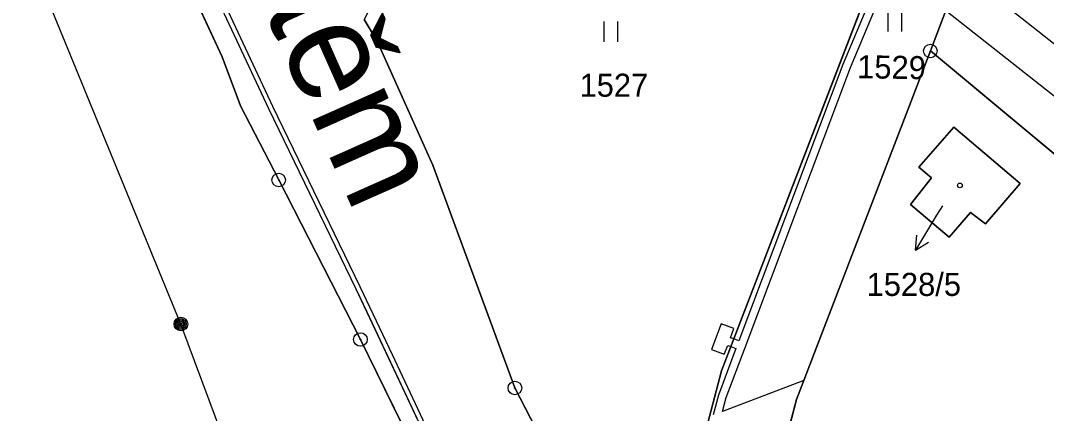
# Model space of a CAD drawing. Extents: x -689422 to -685210, y -987725 to -982160.
# Drawn here: x -687751.8 to -687676.3, y -985280.3 to -985251.4 of the extents above; entities that cross this region are included whole.
import ezdxf

# ---------------------------------------------------------------- set-up
doc = ezdxf.new("R2010")
doc.units = 0
for name, color, linetype in [('KN_Budovy', 7, 'Continuous'), ('KN_Hranice_parcel', 7, 'Continuous'), ('KN_Parcelni cisla', 7, 'Continuous'), ('KN_Parcelni cisla_sipky', 7, 'Continuous'), ('KN_Polygon parcely', 7, 'Continuous'), ('KN_Popisy_pomistni nazvy nazvy ulic', 7, 'Continuous'), ('KN_Pozemkove predmety', 7, 'Continuous'), ('KN_POZEMKY_ORNA PUDA', 7, 'Continuous'), ('KN_POZEMKY_OSTATNI PLOCHA', 7, 'Continuous'), ('KN_POZEMKY_TTP', 7, 'Continuous'), ('KN_POZEMKY_ZASTAVENA PLOCHA', 7, 'Continuous'), ('KN_VYUZITI_17_ostatni plocha_ostatni komunikace', 7, 'Continuous'), ('KN_Věcná břemena k části', 7, 'Continuous'), ('KN_Značky bodu BP', 7, 'Continuous'), ('KN_Značky budov', 7, 'Continuous'), ('KN_Značky kultur', 7, 'Continuous')]:
    doc.layers.add(name, color=color, linetype=linetype)

msp = doc.modelspace()

# ---------------------------------------------------------------- linework, layer by layer
at = {"layer": 'KN_Budovy'}
msp.add_lwpolyline([(-687685.66, -985262.2), (-687684.72, -985263), (-687686.28, -985264.95), (-687683.43, -985267.36), (-687681.85, -985265.54), (-687680.76, -985266.39), (-687678.19, -985263.41), (-687683.07, -985259.26)], close=True, dxfattribs=at)
at = {"layer": 'KN_Hranice_parcel'}
msp.add_line((-687684.81, -985253.65), (-687660.69, -985273.71), dxfattribs=at)
for points in [[(-687678.29, -985374.8), (-687680.11, -985371.33), (-687690.18, -985350.53), (-687698.39, -985334.89), (-687706.44, -985319.16), (-687712.04, -985306.92), (-687713.81, -985302.68), (-687714.34, -985301.44), (-687721.19, -985286.31), (-687726.79, -985274.9), (-687732.81, -985263.15), (-687735.61, -985257.68), (-687736.98, -985254.09), (-687739.8, -985247.97), (-687746.27, -985237.32), (-687750.23, -985231.18), (-687753.34, -985220.89), (-687754.9, -985213.17), (-687756.81, -985206.35), (-687758.16, -985197.59), (-687758.19, -985196.42)], [(-687684.81, -985253.65), (-687683.66, -985250.66), (-687677.81, -985238.56)], [(-687705.55, -985297.58), (-687700.19, -985277.21), (-687689.27, -985248.82)], [(-687726.51, -985251.33), (-687725.56, -985252.93), (-687721.45, -985262.05), (-687715.41, -985278.47), (-687705.55, -985297.58)], [(-687701.56, -985305.65), (-687698.06, -985292.26), (-687694.68, -985279.32), (-687684.81, -985253.65)], [(-687683.43, -985267.36), (-687686.28, -985264.95), (-687684.72, -985263), (-687685.66, -985262.2), (-687683.07, -985259.26), (-687678.19, -985263.41), (-687680.76, -985266.39), (-687681.85, -985265.54), (-687683.43, -985267.36)]]:
    msp.add_lwpolyline(points, dxfattribs=at)
at = {"layer": 'KN_Parcelni cisla_sipky'}
for p, q in [((-687683.92, -985265.05), (-687684.35, -985265.75)), ((-687684.35, -985265.75), (-687685.896, -985268.322)), ((-687685.896, -985268.322), (-687685.809, -985267.206)), ((-687685.896, -985268.322), (-687684.951, -985267.722))]:
    msp.add_line(p, q, dxfattribs=at)
at = {"layer": 'KN_Polygon parcely'}
for points in [[(-687703.73, -985301.1), (-687701.56, -985305.65), (-687698.06, -985292.26), (-687694.68, -985279.32), (-687684.81, -985253.65), (-687683.66, -985250.66), (-687677.81, -985238.56), (-687665.95, -985214.02), (-687671.26, -985211.45), (-687689.27, -985248.82), (-687700.19, -985277.21), (-687705.55, -985297.58)], [(-687700.19, -985277.21), (-687689.27, -985248.82), (-687710.55, -985219.47), (-687726.51, -985251.33), (-687725.56, -985252.93), (-687721.45, -985262.05), (-687715.41, -985278.47), (-687705.55, -985297.58)], [(-687660.69, -985273.71), (-687649.8, -985254.23), (-687655.11, -985251.26), (-687677.81, -985238.56), (-687683.66, -985250.66), (-687684.81, -985253.65)], [(-687660.69, -985273.71), (-687684.81, -985253.65), (-687694.68, -985279.32), (-687698.06, -985292.26), (-687701.56, -985305.65), (-687697.77, -985313.58), (-687696.15, -985316.45), (-687692.92, -985322.65), (-687657.88, -985303.61), (-687653.06, -985312.83), (-687645.42, -985295.51), (-687642.23, -985289.06)], [(-687683.43, -985267.36), (-687681.85, -985265.54), (-687680.76, -985266.39), (-687678.19, -985263.41), (-687683.07, -985259.26), (-687685.66, -985262.2), (-687684.72, -985263), (-687686.28, -985264.95)], [(-687683.43, -985267.36), (-687686.28, -985264.95), (-687684.72, -985263), (-687685.66, -985262.2), (-687683.07, -985259.26), (-687678.19, -985263.41), (-687680.76, -985266.39), (-687681.85, -985265.54)]]:
    msp.add_lwpolyline(points, close=True, dxfattribs=at)
for points in [[(-687690.18, -985350.53), (-687698.39, -985334.89), (-687706.44, -985319.16), (-687712.04, -985306.92), (-687713.81, -985302.68), (-687714.34, -985301.44), (-687721.19, -985286.31), (-687726.79, -985274.9), (-687732.81, -985263.15), (-687735.61, -985257.68), (-687736.98, -985254.09), (-687739.8, -985247.97)], [(-687739.8, -985247.97), (-687736.98, -985254.09), (-687735.61, -985257.68), (-687732.81, -985263.15), (-687726.79, -985274.9), (-687721.19, -985286.31), (-687714.34, -985301.44), (-687713.81, -985302.68), (-687712.04, -985306.92), (-687706.44, -985319.16), (-687698.39, -985334.89), (-687690.18, -985350.53)], [(-687678.56, -985352.38), (-687688.04, -985332.02), (-687692.92, -985322.65), (-687696.15, -985316.45), (-687697.77, -985313.58), (-687701.56, -985305.65), (-687703.73, -985301.1), (-687705.55, -985297.58), (-687715.41, -985278.47), (-687721.45, -985262.05), (-687725.56, -985252.93), (-687726.51, -985251.33)]]:
    msp.add_lwpolyline(points, dxfattribs=at)
at = {"layer": 'KN_Pozemkove predmety'}
for p, q in [((-687740.01, -985273.76), (-687767.2, -985207.53)), ((-687732.51, -985293.95), (-687740.01, -985273.76))]:
    msp.add_line(p, q, dxfattribs=at)
for radius in [0.5, 0.4, 0.3, 0.2, 0.1]:
    msp.add_circle((-687740.013, -985273.76), radius, dxfattribs=at)
at = {"layer": 'KN_POZEMKY_ORNA PUDA'}
for p, q in [((-687684.81, -985253.65), (-687683.66, -985250.66)), ((-687660.69, -985273.71), (-687684.81, -985253.65))]:
    msp.add_line(p, q, dxfattribs=at)
at = {"layer": 'KN_POZEMKY_OSTATNI PLOCHA'}
for p, q in [((-687736.98, -985254.09), (-687739.8, -985247.97)), ((-687726.51, -985251.33), (-687725.56, -985252.93)), ((-687725.56, -985252.93), (-687721.45, -985262.05)), ((-687735.61, -985257.68), (-687736.98, -985254.09)), ((-687732.81, -985263.15), (-687735.61, -985257.68)), ((-687721.45, -985262.05), (-687715.41, -985278.47)), ((-687726.79, -985274.9), (-687732.81, -985263.15)), ((-687721.19, -985286.31), (-687726.79, -985274.9)), ((-687715.41, -985278.47), (-687705.55, -985297.58))]:
    msp.add_line(p, q, dxfattribs=at)
at = {"layer": 'KN_POZEMKY_TTP'}
for p, q in [((-687739.8, -985247.97), (-687736.98, -985254.09)), ((-687689.27, -985248.82), (-687700.19, -985277.21)), ((-687700.19, -985277.21), (-687689.27, -985248.82)), ((-687683.66, -985250.66), (-687684.81, -985253.65)), ((-687725.56, -985252.93), (-687726.51, -985251.33)), ((-687721.45, -985262.05), (-687725.56, -985252.93)), ((-687684.81, -985253.65), (-687694.68, -985279.32)), ((-687694.68, -985279.32), (-687684.81, -985253.65)), ((-687684.81, -985253.65), (-687660.69, -985273.71)), ((-687736.98, -985254.09), (-687735.61, -985257.68)), ((-687735.61, -985257.68), (-687732.81, -985263.15)), ((-687683.07, -985259.26), (-687685.66, -985262.2)), ((-687678.19, -985263.41), (-687683.07, -985259.26)), ((-687715.41, -985278.47), (-687721.45, -985262.05)), ((-687685.66, -985262.2), (-687684.72, -985263)), ((-687732.81, -985263.15), (-687726.79, -985274.9)), ((-687684.72, -985263), (-687686.28, -985264.95)), ((-687680.76, -985266.39), (-687678.19, -985263.41)), ((-687686.28, -985264.95), (-687683.43, -985267.36)), ((-687683.43, -985267.36), (-687681.85, -985265.54)), ((-687681.85, -985265.54), (-687680.76, -985266.39)), ((-687726.79, -985274.9), (-687721.19, -985286.31)), ((-687700.19, -985277.21), (-687705.55, -985297.58)), ((-687705.55, -985297.58), (-687700.19, -985277.21)), ((-687705.55, -985297.58), (-687715.41, -985278.47)), ((-687694.68, -985279.32), (-687698.06, -985292.26)), ((-687698.06, -985292.26), (-687694.68, -985279.32))]:
    msp.add_line(p, q, dxfattribs=at)
at = {"layer": 'KN_POZEMKY_ZASTAVENA PLOCHA'}
for p, q in [((-687685.66, -985262.2), (-687683.07, -985259.26)), ((-687683.07, -985259.26), (-687678.19, -985263.41)), ((-687684.72, -985263), (-687685.66, -985262.2)), ((-687686.28, -985264.95), (-687684.72, -985263)), ((-687678.19, -985263.41), (-687680.76, -985266.39)), ((-687683.43, -985267.36), (-687686.28, -985264.95)), ((-687681.85, -985265.54), (-687683.43, -985267.36)), ((-687680.76, -985266.39), (-687681.85, -985265.54))]:
    msp.add_line(p, q, dxfattribs=at)
at = {"layer": 'KN_VYUZITI_17_ostatni plocha_ostatni komunikace'}
for p, q in [((-687736.98, -985254.09), (-687739.8, -985247.97)), ((-687726.51, -985251.33), (-687725.56, -985252.93)), ((-687725.56, -985252.93), (-687721.45, -985262.05)), ((-687735.61, -985257.68), (-687736.98, -985254.09)), ((-687732.81, -985263.15), (-687735.61, -985257.68)), ((-687721.45, -985262.05), (-687715.41, -985278.47)), ((-687726.79, -985274.9), (-687732.81, -985263.15)), ((-687721.19, -985286.31), (-687726.79, -985274.9)), ((-687715.41, -985278.47), (-687705.55, -985297.58))]:
    msp.add_line(p, q, dxfattribs=at)
at = {"layer": 'KN_Věcná břemena k části'}
for points in [[(-687688.04, -985246.99), (-687691.26, -985254.65), (-687698.92, -985274.99)], [(-687695.26, -985281.55), (-687694.68, -985279.32), (-687694.14, -985277.91), (-687700.11, -985280.2), (-687699.84, -985279.17), (-687698.46, -985275.49), (-687690.7, -985254.87), (-687687.5, -985247.23)], [(-687737.93, -985248.53), (-687733.55, -985257.89), (-687727.12, -985271.16), (-687719.31, -985287.75), (-687712.27, -985302.31), (-687705.97, -985315.48), (-687702.96, -985321.78), (-687699.44, -985329.15), (-687697.08, -985334.1), (-687696.27, -985335.82), (-687694.15, -985340.61)], [(-687737.93, -985248.53), (-687733.55, -985257.89), (-687727.12, -985271.16), (-687726.32, -985272.86), (-687719.31, -985287.75), (-687712.27, -985302.31), (-687705.97, -985315.48), (-687702.96, -985321.78), (-687699.44, -985329.15), (-687697.08, -985334.1), (-687696.27, -985335.82), (-687694.15, -985340.61)], [(-687693.82, -985340.5), (-687695.95, -985335.67), (-687696.77, -985333.95), (-687700.05, -985327.07), (-687702.64, -985321.63), (-687711.96, -985302.16), (-687719, -985287.6), (-687724.43, -985276.04), (-687726.8, -985271.01), (-687733.24, -985257.74), (-687737.61, -985248.38)], [(-687693.82, -985340.5), (-687695.95, -985335.67), (-687696.77, -985333.95), (-687700.05, -985327.07), (-687702.64, -985321.63), (-687711.96, -985302.16), (-687719, -985287.6), (-687724.43, -985276.04), (-687726.8, -985271.01), (-687733.24, -985257.74), (-687737.61, -985248.38)], [(-687698.92, -985274.99), (-687699.29, -985274.86), (-687699.5, -985275.42), (-687699.13, -985275.56), (-687700.42, -985278.99), (-687700.8, -985280.46)]]:
    msp.add_lwpolyline(points, dxfattribs=at)
for points in [[(-687683.66, -985250.66), (-687668.5, -985262.63), (-687658.25, -985269.35), (-687656.78, -985266.72), (-687666.74, -985260.19), (-687682.32, -985247.89)], [(-687700.93, -985275.63), (-687699.99, -985275.98), (-687699.74, -985275.33), (-687699.5, -985275.42), (-687699.29, -985274.86), (-687699.53, -985274.77), (-687699.28, -985274.1), (-687700.22, -985273.75)]]:
    msp.add_lwpolyline(points, close=True, dxfattribs=at)
at = {"layer": 'KN_Značky bodu BP'}
for centre, radius in [((-687684.81, -985253.65), 0.5), ((-687684.81, -985253.65), 0.0303), ((-687732.81, -985263.15), 0.5), ((-687732.81, -985263.15), 0.0303), ((-687726.79, -985274.9), 0.5), ((-687726.79, -985274.9), 0.0303), ((-687715.41, -985278.47), 0.5), ((-687715.41, -985278.47), 0.0303)]:
    msp.add_circle(centre, radius, dxfattribs=at)
at = {"layer": 'KN_Značky budov'}
msp.add_circle((-687682.637, -985263.549), 0.175, dxfattribs=at)
at = {"layer": 'KN_Značky kultur'}
for p, q in [((-687687.911, -985252.21), (-687687.911, -985250.71)), ((-687686.91, -985252.21), (-687686.91, -985250.71)), ((-687708.841, -985252.98), (-687708.841, -985251.48)), ((-687707.84, -985252.98), (-687707.84, -985251.48))]:
    msp.add_line(p, q, dxfattribs=at)

# ---------------------------------------------------------------- texts
at = {"layer": 'KN_Parcelni cisla'}
msp.add_text('1529', height=1.7, rotation=359, dxfattribs=at).set_placement((-687690.214, -985255.649))
for s, p in [('1527', (-687710.65, -985257.02)), ('1528/5', (-687689.507, -985271.69))]:
    msp.add_text(s, height=1.7, dxfattribs=at).set_placement(p)
at = {"layer": 'KN_Popisy_pomistni nazvy nazvy ulic'}
msp.add_text('Pod Letištěm', height=7.5, rotation=294, dxfattribs=at).set_placement((-687750.991, -985212.249))

doc.saveas('drawing.dxf')
